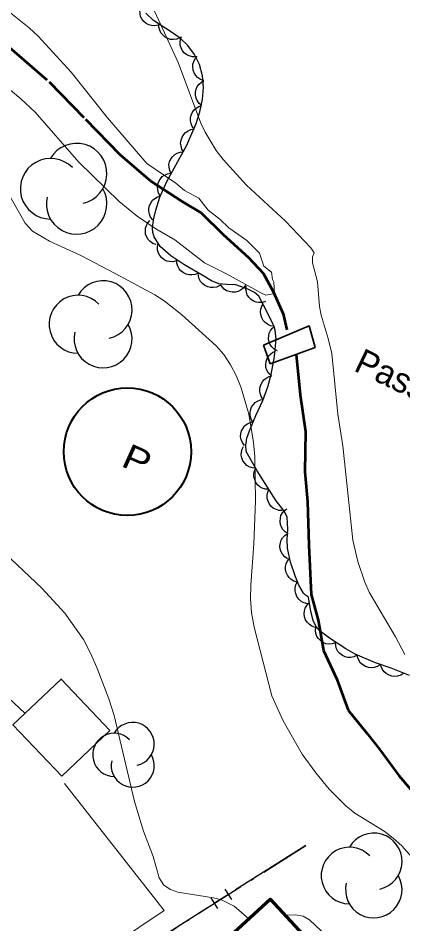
# Model space of a CAD drawing. Extents: x 356765 to 358572, y 5103174 to 5104650.
# Drawn here: x 357624.3 to 357647.4, y 5103719.2 to 5103773.6 of the extents above; entities that cross this region are included whole.
import ezdxf

# ---------------------------------------------------------------- set-up
doc = ezdxf.new("R2010")
doc.units = 0
doc.header["$LTSCALE"] = 0.6
doc.linetypes.add('DASH_DOUBLE_DOT', pattern=[9.2, 5, -1.2, 0.3, -1.2, 0.3, -1.2])
doc.linetypes.add('DOT_DASHED', pattern=[7.7, 5, -1.2, 0.3, -1.2])
for name, color, linetype, lineweight in [('19', 7, 'Continuous', 13), ('2', 7, 'Continuous', 13), ('26', 7, 'Continuous', 35), ('31', 7, 'Continuous', 70), ('37', 7, 'Continuous', 13), ('38', 7, 'Continuous', 40), ('4', 7, 'Continuous', 90), ('44', 7, 'Continuous', 25)]:
    doc.layers.add(name, color=color, linetype=linetype, lineweight=lineweight)

msp = doc.modelspace()

# ---------------------------------------------------------------- linework, layer by layer
at = {"layer": '19'}
msp.add_line((357624.7, 5103731.84), (357612.81, 5103742.9), dxfattribs=at)
msp.add_lwpolyline([(357602.77, 5103700.19), (357604.55, 5103701.95), (357616.08, 5103708.59), (357633.09, 5103719.97), (357627.09, 5103727.61)], dxfattribs=at)
at = {"layer": '2'}
for points in [[(357622.57, 5103770.32), (357624.47, 5103768.74), (357625.32, 5103767.93), (357627.96, 5103764.93), (357630.37, 5103762.57), (357631.45, 5103761.69), (357632.58, 5103760.93), (357633.73, 5103760.26), (357635.51, 5103758.88), (357636.82, 5103758.22), (357638.89, 5103757.08), (357639.19, 5103756.93), (357639.72, 5103757.03), (357639.67, 5103757.71), (357639.6, 5103757.88), (357639.54, 5103758.32), (357639.07, 5103758.69), (357638.81, 5103759.47), (357638.05, 5103760.23), (357636.97, 5103760.99), (357636.42, 5103761.51), (357635.72, 5103762.04), (357635.16, 5103762.76), (357634.31, 5103763.22), (357633.78, 5103763.67), (357632.03, 5103764.84), (357629.68, 5103767.59), (357627.5, 5103770.34), (357625.51, 5103772.49), (357624.96, 5103773), (357623.87, 5103773.88)], [(357647.54, 5103735.36), (357646.99, 5103736.42), (357645.4, 5103739.09), (357645.14, 5103739.69), (357644.72, 5103740.94), (357644.43, 5103742.23), (357643.81, 5103747.88), (357643.51, 5103749.8), (357643.15, 5103753.44), (357642.94, 5103754.34), (357642.51, 5103755.74), (357642.42, 5103756.26), (357642.29, 5103757.73), (357641.99, 5103758.88), (357642, 5103759.24), (357642.1, 5103759.49), (357641.9, 5103759.79), (357640.37, 5103761.38), (357638.02, 5103763.54), (357636.62, 5103765.09), (357636.2, 5103765.62), (357635.54, 5103766.73), (357635.29, 5103767.26), (357633.93, 5103770.92), (357632.37, 5103774.26)], [(357622.92, 5103764.41), (357624.72, 5103761.26), (357625.16, 5103760.79), (357626.19, 5103760.19), (357628.07, 5103759.32), (357630.13, 5103758.25), (357632.52, 5103756.95), (357633.08, 5103756.59), (357634.12, 5103755.78), (357636.2, 5103753.9), (357636.67, 5103753.38), (357637.07, 5103752.76), (357637.41, 5103752.12), (357637.7, 5103751.38), (357638.17, 5103749.79), (357638.44, 5103748.09), (357638.52, 5103747.22), (357638.57, 5103744.59), (357638.46, 5103742.01), (357638.28, 5103739.51), (357638.27, 5103738.7), (357638.32, 5103737.87), (357638.49, 5103737), (357639.56, 5103732.87), (357640.24, 5103731.38), (357641.37, 5103729.37), (357642.19, 5103728.25), (357643, 5103727.26), (357643.99, 5103726.26), (357644.55, 5103725.83), (357646.3, 5103724.74), (357646.85, 5103724.32), (357647.37, 5103723.87), (357648.27, 5103722.84)], [(357622.74, 5103742.15), (357625.72, 5103739.34), (357627.12, 5103737.84), (357628.23, 5103736.26), (357628.66, 5103735.44), (357629.04, 5103734.57), (357629.75, 5103732.7), (357630.07, 5103731.7), (357631.29, 5103726.53), (357631.84, 5103724.75), (357632.41, 5103723.22), (357632.78, 5103721.93), (357633.07, 5103721.49), (357633.46, 5103721.24), (357633.91, 5103721.08), (357636.05, 5103720.73), (357636.53, 5103720.61), (357637.29, 5103720.24), (357638.16, 5103719.47)], [(357640.34, 5103719.7), (357640.97, 5103719.71), (357641.43, 5103719.63), (357641.82, 5103719.42), (357642.51, 5103718.76), (357644.86, 5103715.94), (357645.52, 5103714.98), (357645.75, 5103714.46), (357645.89, 5103713.87), (357645.91, 5103713.23), (357645.82, 5103712.55), (357645.33, 5103711.15), (357645.02, 5103710.47), (357644.11, 5103708.71), (357643.76, 5103708.26), (357643.33, 5103707.93), (357642.83, 5103707.69), (357642.53, 5103707.6)]]:
    msp.add_lwpolyline(points, dxfattribs=at)
at = {"layer": '26'}
msp.add_lwpolyline([(357639.05, 5103753.93), (357641.79, 5103755.09), (357642.15, 5103753.8), (357639.46, 5103752.82)], close=True, dxfattribs=at)
at = {"layer": '31', "lineweight": 35}
msp.add_lwpolyline([(357626.92, 5103728.05), (357623.99, 5103731.13), (357626.88, 5103733.88), (357629.81, 5103730.79), (357626.92, 5103728.05)], close=True, dxfattribs=at)
at = {"layer": '31'}
msp.add_lwpolyline([(357632.26, 5103693.84), (357626.05, 5103700.78), (357625.89, 5103701.2), (357625.83, 5103701.7), (357625.84, 5103702.2), (357625.95, 5103702.67), (357626.17, 5103703.09), (357626.56, 5103703.55), (357626.97, 5103703.91), (357627.58, 5103704.45), (357636.12, 5103712.5), (357633.6, 5103715.29), (357639.45, 5103720.66), (357645.34, 5103714.3), (357635.4, 5103705.41), (357639.75, 5103700.5), (357632.26, 5103693.84)], close=True, dxfattribs=at)
at = {"layer": '37', "linetype": 'DOT_DASHED', "lineweight": 25}
msp.add_line((357641.6, 5103723.87), (357630.45, 5103716.8), dxfattribs=at)
at = {"layer": '37', "lineweight": 25}
for p, q in [((357641.59, 5103723.89), (357637.37, 5103721.21)), ((357637.14, 5103720.63), (357636.74, 5103721.26)), ((357636.3, 5103720.09), (357635.9, 5103720.73)), ((357636.95, 5103720.94), (357636.1, 5103720.41)), ((357635.68, 5103720.14), (357631.46, 5103717.46))]:
    msp.add_line(p, q, dxfattribs=at)
at = {"layer": '38'}
msp.add_circle((357630.8746, 5103747.5365), 3.8299, dxfattribs=at)
at = {"layer": '4', "linetype": 'DASH_DOUBLE_DOT', "lineweight": 53}
for points in [[(357620.41, 5103774.86), (357623.76, 5103771.83), (357626.16, 5103769.76), (357628.35, 5103767.51), (357630.41, 5103765.38), (357632.28, 5103763.78), (357634.17, 5103762.57), (357635.3, 5103761.88), (357636.63, 5103760.59), (357638.14, 5103759.2), (357639.04, 5103758.26), (357639.64, 5103757.15), (357640.24, 5103755.82), (357640.45, 5103754.86)], [(357641.01, 5103753.38), (357641.26, 5103750.96), (357641.58, 5103748.74), (357641.54, 5103746.32), (357641.7, 5103744.54), (357641.78, 5103741.93), (357641.91, 5103738.96), (357642.34, 5103737.42), (357642.65, 5103735.59), (357643.46, 5103733.88), (357644.14, 5103732.01), (357645.26, 5103730.63), (357646.03, 5103729.67), (357647.18, 5103728.09), (357648.47, 5103726.59)]]:
    msp.add_lwpolyline(points, dxfattribs=at)
at = {"layer": '44'}
for points in [[(357632.72, 5103773.16), (357632.52, 5103773.11), (357632.31, 5103773.13), (357632.15, 5103773.17), (357632, 5103773.26), (357631.86, 5103773.37), (357631.74, 5103773.53), (357631.66, 5103773.67), (357631.63, 5103773.84), (357631.62, 5103774.03), (357631.65, 5103774.2)], [(357634.03, 5103772.4), (357633.84, 5103772.32), (357633.63, 5103772.3), (357633.47, 5103772.3), (357633.3, 5103772.36), (357633.14, 5103772.44), (357633, 5103772.57), (357632.89, 5103772.7), (357632.82, 5103772.86), (357632.77, 5103773.04), (357632.77, 5103773.22)], [(357635, 5103771.26), (357634.79, 5103771.26), (357634.59, 5103771.31), (357634.44, 5103771.37), (357634.31, 5103771.48), (357634.19, 5103771.62), (357634.1, 5103771.8), (357634.04, 5103771.95), (357634.04, 5103772.13), (357634.06, 5103772.31), (357634.12, 5103772.48)], [(357635.46, 5103769.83), (357635.26, 5103769.9), (357635.09, 5103770.02), (357634.98, 5103770.14), (357634.89, 5103770.29), (357634.82, 5103770.46), (357634.81, 5103770.65), (357634.81, 5103770.82), (357634.86, 5103770.98), (357634.95, 5103771.15), (357635.07, 5103771.28)], [(357635.35, 5103768.33), (357635.19, 5103768.46), (357635.07, 5103768.63), (357635, 5103768.78), (357634.97, 5103768.95), (357634.97, 5103769.13), (357635.01, 5103769.32), (357635.07, 5103769.47), (357635.18, 5103769.61), (357635.32, 5103769.74), (357635.47, 5103769.83)], [(357634.9, 5103766.89), (357634.77, 5103767.06), (357634.7, 5103767.25), (357634.66, 5103767.41), (357634.66, 5103767.58), (357634.7, 5103767.76), (357634.79, 5103767.93), (357634.88, 5103768.07), (357635.01, 5103768.18), (357635.17, 5103768.27), (357635.35, 5103768.33)], [(357634.26, 5103765.53), (357634.15, 5103765.71), (357634.1, 5103765.91), (357634.07, 5103766.07), (357634.1, 5103766.24), (357634.16, 5103766.42), (357634.27, 5103766.58), (357634.37, 5103766.71), (357634.52, 5103766.8), (357634.69, 5103766.88), (357634.86, 5103766.91)], [(357633.51, 5103764.23), (357633.42, 5103764.42), (357633.38, 5103764.62), (357633.37, 5103764.78), (357633.41, 5103764.95), (357633.49, 5103765.12), (357633.6, 5103765.27), (357633.72, 5103765.39), (357633.87, 5103765.47), (357634.05, 5103765.53), (357634.23, 5103765.55)], [(357632.85, 5103762.89), (357632.74, 5103763.06), (357632.69, 5103763.26), (357632.67, 5103763.42), (357632.7, 5103763.6), (357632.76, 5103763.77), (357632.86, 5103763.93), (357632.96, 5103764.06), (357633.11, 5103764.15), (357633.28, 5103764.23), (357633.46, 5103764.26)], [(357632.39, 5103761.46), (357632.26, 5103761.62), (357632.19, 5103761.81), (357632.15, 5103761.97), (357632.16, 5103762.15), (357632.2, 5103762.33), (357632.29, 5103762.5), (357632.38, 5103762.64), (357632.51, 5103762.75), (357632.68, 5103762.84), (357632.85, 5103762.89)], [(357632.59, 5103759.98), (357632.39, 5103760.05), (357632.23, 5103760.17), (357632.11, 5103760.28), (357632.03, 5103760.43), (357631.96, 5103760.61), (357631.95, 5103760.8), (357631.95, 5103760.96), (357632.01, 5103761.13), (357632.1, 5103761.29), (357632.21, 5103761.43)], [(357633.81, 5103759.01), (357633.61, 5103758.95), (357633.41, 5103758.96), (357633.24, 5103758.99), (357633.09, 5103759.07), (357632.94, 5103759.18), (357632.82, 5103759.33), (357632.73, 5103759.47), (357632.68, 5103759.64), (357632.67, 5103759.82), (357632.69, 5103760)], [(357635.13, 5103758.27), (357634.94, 5103758.18), (357634.74, 5103758.15), (357634.57, 5103758.15), (357634.4, 5103758.2), (357634.24, 5103758.28), (357634.09, 5103758.41), (357633.98, 5103758.52), (357633.9, 5103758.68), (357633.85, 5103758.86), (357633.84, 5103759.04)], [(357636.42, 5103757.51), (357636.23, 5103757.42), (357636.03, 5103757.39), (357635.87, 5103757.39), (357635.7, 5103757.44), (357635.53, 5103757.52), (357635.38, 5103757.64), (357635.27, 5103757.76), (357635.19, 5103757.91), (357635.14, 5103758.09), (357635.13, 5103758.27)], [(357637.96, 5103757.53), (357637.84, 5103757.36), (357637.67, 5103757.24), (357637.53, 5103757.16), (357637.36, 5103757.12), (357637.17, 5103757.11), (357636.99, 5103757.15), (357636.83, 5103757.2), (357636.69, 5103757.3), (357636.56, 5103757.43), (357636.46, 5103757.58)], [(357639.18, 5103756.55), (357638.98, 5103756.49), (357638.78, 5103756.49), (357638.62, 5103756.51), (357638.45, 5103756.58), (357638.3, 5103756.68), (357638.17, 5103756.82), (357638.07, 5103756.95), (357638.02, 5103757.12), (357637.99, 5103757.3), (357638, 5103757.48)], [(357639.68, 5103755.07), (357639.47, 5103755.1), (357639.29, 5103755.19), (357639.15, 5103755.29), (357639.04, 5103755.42), (357638.95, 5103755.58), (357638.9, 5103755.77), (357638.87, 5103755.93), (357638.9, 5103756.1), (357638.95, 5103756.28), (357639.05, 5103756.43)], [(357639.89, 5103753.59), (357639.7, 5103753.69), (357639.56, 5103753.83), (357639.46, 5103753.96), (357639.39, 5103754.13), (357639.36, 5103754.31), (357639.37, 5103754.5), (357639.4, 5103754.66), (357639.48, 5103754.82), (357639.59, 5103754.96), (357639.72, 5103755.08)], [(357639.51, 5103752.11), (357639.36, 5103752.26), (357639.26, 5103752.43), (357639.2, 5103752.59), (357639.19, 5103752.76), (357639.21, 5103752.95), (357639.27, 5103753.13), (357639.34, 5103753.27), (357639.47, 5103753.4), (357639.62, 5103753.51), (357639.78, 5103753.58)], [(357639.04, 5103750.68), (357638.92, 5103750.85), (357638.86, 5103751.05), (357638.83, 5103751.21), (357638.84, 5103751.38), (357638.89, 5103751.56), (357638.99, 5103751.73), (357639.08, 5103751.86), (357639.22, 5103751.96), (357639.39, 5103752.05), (357639.56, 5103752.09)], [(357638.41, 5103749.33), (357638.3, 5103749.5), (357638.25, 5103749.7), (357638.24, 5103749.87), (357638.27, 5103750.04), (357638.33, 5103750.21), (357638.44, 5103750.37), (357638.55, 5103750.49), (357638.7, 5103750.58), (357638.87, 5103750.65), (357639.05, 5103750.68)], [(357637.9, 5103747.91), (357637.78, 5103748.08), (357637.71, 5103748.27), (357637.67, 5103748.43), (357637.68, 5103748.61), (357637.73, 5103748.79), (357637.82, 5103748.95), (357637.91, 5103749.09), (357638.05, 5103749.2), (357638.21, 5103749.28), (357638.39, 5103749.33)], [(357638.59, 5103746.55), (357638.38, 5103746.56), (357638.19, 5103746.63), (357638.04, 5103746.71), (357637.92, 5103746.84), (357637.81, 5103746.99), (357637.75, 5103747.17), (357637.71, 5103747.33), (357637.72, 5103747.5), (357637.76, 5103747.69), (357637.84, 5103747.85)], [(357639.38, 5103745.28), (357639.17, 5103745.28), (357638.98, 5103745.35), (357638.83, 5103745.42), (357638.7, 5103745.54), (357638.59, 5103745.68), (357638.52, 5103745.86), (357638.47, 5103746.02), (357638.47, 5103746.19), (357638.51, 5103746.38), (357638.58, 5103746.54)], [(357640.18, 5103744), (357639.97, 5103744.01), (357639.77, 5103744.08), (357639.63, 5103744.15), (357639.5, 5103744.27), (357639.39, 5103744.42), (357639.32, 5103744.6), (357639.27, 5103744.75), (357639.28, 5103744.93), (357639.31, 5103745.11), (357639.38, 5103745.28)], [(357640.53, 5103742.61), (357640.36, 5103742.72), (357640.22, 5103742.87), (357640.13, 5103743), (357640.07, 5103743.17), (357640.05, 5103743.35), (357640.07, 5103743.55), (357640.1, 5103743.7), (357640.19, 5103743.86), (357640.31, 5103744), (357640.45, 5103744.11)], [(357640.5, 5103741.11), (357640.33, 5103741.23), (357640.2, 5103741.38), (357640.11, 5103741.52), (357640.06, 5103741.69), (357640.04, 5103741.87), (357640.07, 5103742.06), (357640.11, 5103742.22), (357640.2, 5103742.37), (357640.33, 5103742.51), (357640.47, 5103742.61)], [(357641.09, 5103739.7), (357640.88, 5103739.75), (357640.71, 5103739.86), (357640.59, 5103739.97), (357640.49, 5103740.12), (357640.41, 5103740.29), (357640.38, 5103740.47), (357640.38, 5103740.64), (357640.42, 5103740.81), (357640.5, 5103740.98), (357640.61, 5103741.12)], [(357641.84, 5103738.4), (357641.63, 5103738.41), (357641.44, 5103738.48), (357641.29, 5103738.56), (357641.17, 5103738.68), (357641.06, 5103738.83), (357640.99, 5103739.01), (357640.95, 5103739.17), (357640.96, 5103739.35), (357641, 5103739.53), (357641.07, 5103739.69)], [(357642.15, 5103736.98), (357641.95, 5103737.05), (357641.79, 5103737.17), (357641.67, 5103737.29), (357641.58, 5103737.44), (357641.52, 5103737.61), (357641.5, 5103737.8), (357641.51, 5103737.97), (357641.56, 5103738.13), (357641.65, 5103738.3), (357641.77, 5103738.43)], [(357643.37, 5103736.05), (357643.17, 5103735.99), (357642.97, 5103735.98), (357642.8, 5103736), (357642.64, 5103736.07), (357642.49, 5103736.17), (357642.36, 5103736.31), (357642.26, 5103736.44), (357642.2, 5103736.61), (357642.17, 5103736.79), (357642.19, 5103736.97)], [(357644.68, 5103735.31), (357644.49, 5103735.22), (357644.29, 5103735.18), (357644.12, 5103735.18), (357643.95, 5103735.22), (357643.79, 5103735.3), (357643.64, 5103735.42), (357643.52, 5103735.54), (357643.44, 5103735.69), (357643.39, 5103735.87), (357643.37, 5103736.05)], [(357646.07, 5103734.74), (357645.89, 5103734.63), (357645.7, 5103734.57), (357645.53, 5103734.55), (357645.36, 5103734.57), (357645.18, 5103734.63), (357645.02, 5103734.73), (357644.89, 5103734.83), (357644.8, 5103734.98), (357644.72, 5103735.15), (357644.68, 5103735.32)], [(357647.48, 5103734.23), (357647.3, 5103734.12), (357647.11, 5103734.06), (357646.95, 5103734.03), (357646.77, 5103734.06), (357646.6, 5103734.11), (357646.43, 5103734.21), (357646.3, 5103734.31), (357646.2, 5103734.46), (357646.13, 5103734.63), (357646.09, 5103734.8)]]:
    msp.add_lwpolyline(points, dxfattribs=at)
at = {"layer": '44', "linetype": 'DOT_DASHED'}
for points in [[(357632.85, 5103759.86), (357632.47, 5103760.44), (357632.4, 5103760.71), (357632.38, 5103760.97), (357632.44, 5103761.46), (357632.58, 5103762.05), (357632.83, 5103762.83), (357633.24, 5103763.76), (357633.81, 5103764.78), (357634.44, 5103765.94), (357635.01, 5103767.24), (357635.23, 5103767.95), (357635.38, 5103768.69), (357635.44, 5103769.42), (357635.38, 5103770.12), (357635.2, 5103770.79), (357634.9, 5103771.4), (357634.51, 5103771.94), (357634.05, 5103772.37), (357633.52, 5103772.73), (357632.44, 5103773.43), (357631.98, 5103773.88)], [(357647.83, 5103734.09), (357646.73, 5103734.54), (357645.79, 5103734.86), (357644.57, 5103735.37), (357643.99, 5103735.7), (357643.01, 5103736.33), (357642.46, 5103736.76), (357642.19, 5103737.05), (357642.04, 5103737.4), (357641.9, 5103737.93), (357641.75, 5103738.8), (357641.57, 5103738.91), (357641.46, 5103739.04), (357641.18, 5103739.51), (357640.96, 5103740.07), (357640.68, 5103740.9), (357640.49, 5103741.74), (357640.48, 5103742.24), (357640.52, 5103742.88), (357640.48, 5103743.61), (357640.31, 5103743.94), (357639.81, 5103744.59), (357639.4, 5103745.25), (357638.68, 5103746.38), (357638.01, 5103747.55), (357637.99, 5103747.93), (357638.05, 5103748.34), (357638.2, 5103748.78), (357638.59, 5103749.71), (357639.02, 5103750.62), (357639.32, 5103751.43), (357639.52, 5103752.18), (357639.72, 5103753.26), (357639.81, 5103754.29), (357639.75, 5103754.84), (357639.67, 5103755.09), (357639.34, 5103755.8), (357638.78, 5103756.87), (357638.5, 5103757.09), (357638.1, 5103757.3), (357637.38, 5103757.55), (357636.83, 5103757.57), (357636.36, 5103757.62), (357635.93, 5103757.8), (357635.37, 5103758.13), (357634.26, 5103758.79), (357633.48, 5103759.3), (357632.85, 5103759.86)]]:
    msp.add_lwpolyline(points, dxfattribs=at)
at = {"layer": '44'}
for centre, radius, start, end in [((357627.8198, 5103764.2409), 1.8192, 282.26917, 149.72626), ((357626.2553, 5103763.3313), 1.8192, 44.11537, 269.80396), ((357627.8198, 5103762.4217), 1.8192, 166.93686, 29.62122), ((357629.4079, 5103756.061), 1.7429, 282.26917, 149.72626), ((357627.9091, 5103755.1896), 1.7429, 44.11537, 269.80396), ((357629.4079, 5103754.3181), 1.7429, 166.93686, 29.62122), ((357631.1907, 5103729.9767), 1.2945, 282.26917, 149.72626), ((357630.0774, 5103729.3294), 1.2945, 44.11537, 269.80396), ((357631.1907, 5103728.6821), 1.2945, 166.93686, 29.62122), ((357645.6794, 5103722.9278), 1.6984, 282.26917, 149.72626), ((357644.2188, 5103722.0786), 1.6984, 44.11537, 269.80396), ((357645.6794, 5103721.2294), 1.6984, 166.93686, 29.62122)]:
    msp.add_arc(centre, radius, start, end, dxfattribs=at)

# ---------------------------------------------------------------- texts
at = {"layer": '26'}
msp.add_text('Passerelle', height=1.5, rotation=334.422, dxfattribs=at).set_placement((357644.41, 5103752.43))
at = {"layer": '38', "width": 1.2}
msp.add_text('P', height=1.5, rotation=335.78, dxfattribs=at).set_placement((357630.42, 5103746.7))

doc.saveas('drawing.dxf')
